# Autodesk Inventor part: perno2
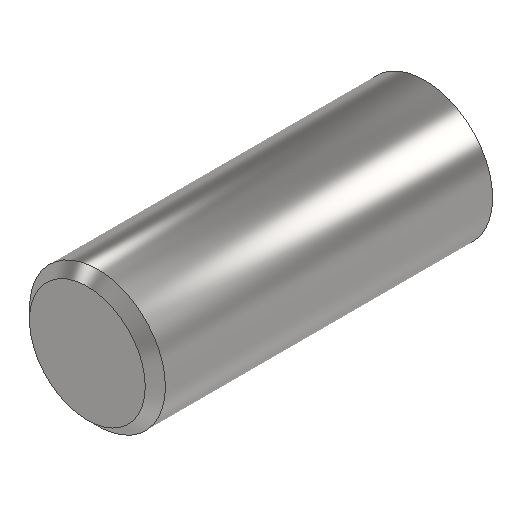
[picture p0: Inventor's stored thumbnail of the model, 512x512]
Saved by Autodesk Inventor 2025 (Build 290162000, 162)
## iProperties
Created: 2025-10
Part Number: perno2
Material: Acciaio inossidabile
Document SubType Name: Modeling
Designer: Ryzen5700u
Density: 8 g/cm^3
Appearance: Semilucidato
Mass: 38.3612 g
Surface Area: 68.2825 cm^2
Volume: 38.3612 cm^3
Author: Ryzen5700u
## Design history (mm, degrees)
node "Piano di lavoro1"
sketch "Schizzo1"
  geometry: C1 r 13.5 at (0, 0); 1 further point
  constraints: 1 centre point, 1 coincident
  dimensions: "d0" = 27 diameter of C1
extrude "Estrusione1" new body sketch "Schizzo1" distance "d1" = 67; taper "d2" = 0 deg
chamfer "Smusso1" distance "d3" = 2; stored, may be unused: second distance "d4" = 2, angle "d5" = 45 deg
node "Solido1"
